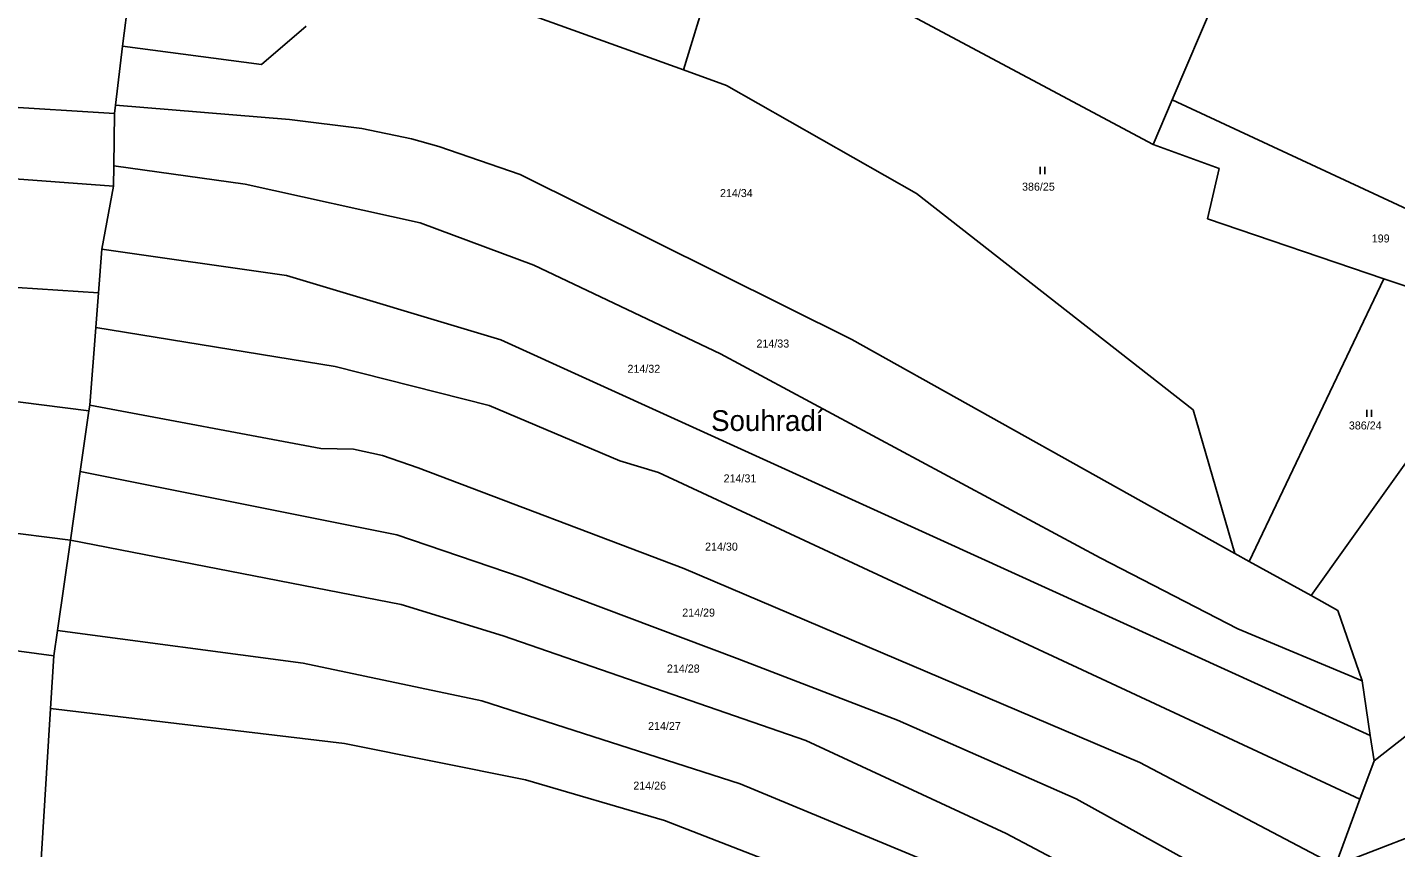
# Model space of a CAD drawing. Extents: x -791032 to -787751, y -1106872 to -1104403.
# Drawn here: x -789521.6 to -789231, y -1105221.6 to -1105047.4 of the extents above; entities that cross this region are included whole.
import ezdxf

# ---------------------------------------------------------------- set-up
doc = ezdxf.new("R2010")
doc.units = 0
for name, color, linetype in [('Vrstva 1', 7, 'Continuous'), ('Vrstva 14', 7, 'Continuous'), ('Vrstva 23', 7, 'Continuous'), ('Vrstva 39', 7, 'Continuous')]:
    doc.layers.add(name, color=color, linetype=linetype)

msp = doc.modelspace()

# ---------------------------------------------------------------- linework, layer by layer
at = {"layer": 'Vrstva 1'}
for p, q in [((-789501.39, -1105051.37), (-789499.01, -1105031.98)), ((-789382.28, -1105056.43), (-789376.17, -1105036.47)), ((-789382.28, -1105056.43), (-789423.8, -1105041.43)), ((-789278.51, -1105062.82), (-789269.38, -1105041.33)), ((-789282.53, -1105072.29), (-789335.91, -1105043.8)), ((-789462.42, -1105047.11), (-789471.88, -1105055.3)), ((-789502.93, -1105063.93), (-789501.39, -1105051.37)), ((-789501.39, -1105051.37), (-789471.88, -1105055.3)), ((-789373.13, -1105059.74), (-789382.28, -1105056.43)), ((-789332.82, -1105082.7), (-789373.13, -1105059.74)), ((-789282.53, -1105072.29), (-789278.51, -1105062.82)), ((-789278.51, -1105062.82), (-789222.93, -1105088.68)), ((-789528.49, -1105064.11), (-789503.15, -1105065.68)), ((-789503.15, -1105065.68), (-789503.28, -1105076.82)), ((-789503.15, -1105065.68), (-789502.93, -1105063.93)), ((-789502.93, -1105063.93), (-789465.99, -1105066.96)), ((-789465.99, -1105066.96), (-789450.6, -1105068.89)), ((-789450.6, -1105068.89), (-789440.07, -1105071.04)), ((-789440.07, -1105071.04), (-789434.22, -1105072.71)), ((-789282.53, -1105072.29), (-789268.5, -1105077.4)), ((-789434.22, -1105072.71), (-789416.96, -1105078.67)), ((-789503.33, -1105081.13), (-789552.47, -1105077.5)), ((-789503.28, -1105076.82), (-789503.33, -1105081.13)), ((-789503.28, -1105076.82), (-789475.35, -1105080.72)), ((-789268.5, -1105077.4), (-789271.02, -1105088.05)), ((-789505.83, -1105094.52), (-789503.33, -1105081.13)), ((-789475.35, -1105080.72), (-789438.22, -1105088.93)), ((-789416.96, -1105078.67), (-789346.54, -1105113.7)), ((-789274.03, -1105128.66), (-789332.82, -1105082.7)), ((-789438.22, -1105088.93), (-789414.08, -1105097.9)), ((-789271.02, -1105088.05), (-789233.54, -1105100.77)), ((-789506.54, -1105103.75), (-789505.83, -1105094.52)), ((-789505.83, -1105094.52), (-789466.58, -1105100.1)), ((-789414.08, -1105097.9), (-789374.45, -1105116.72)), ((-789506.54, -1105103.75), (-789547.8, -1105101.04)), ((-789466.58, -1105100.1), (-789421.07, -1105113.78)), ((-789262.14, -1105160.82), (-789233.54, -1105100.77)), ((-789233.54, -1105100.77), (-789207.36, -1105109.66)), ((-789507.11, -1105111.11), (-789506.54, -1105103.75)), ((-789249, -1105168.08), (-789207.36, -1105109.66)), ((-789508.39, -1105127.62), (-789507.11, -1105111.11)), ((-789507.11, -1105111.11), (-789456.26, -1105119.41)), ((-789327.7, -1105156.26), (-789421.07, -1105113.78)), ((-789346.54, -1105113.7), (-789265.23, -1105159.11)), ((-789374.45, -1105116.72), (-789293.78, -1105160.04)), ((-789456.26, -1105119.41), (-789423.56, -1105127.68)), ((-789508.57, -1105128.87), (-789537.11, -1105125.17)), ((-789508.57, -1105128.87), (-789508.39, -1105127.62)), ((-789508.39, -1105127.62), (-789459.31, -1105136.81)), ((-789423.56, -1105127.68), (-789395.8, -1105139.44)), ((-789510.41, -1105141.76), (-789508.57, -1105128.87)), ((-789274.03, -1105128.66), (-789265.23, -1105159.11)), ((-789459.31, -1105136.81), (-789452.35, -1105136.97)), ((-789452.35, -1105136.97), (-789446.18, -1105138.34)), ((-789446.18, -1105138.34), (-789438.65, -1105140.93)), ((-789512.49, -1105156.3), (-789510.41, -1105141.76)), ((-789510.41, -1105141.76), (-789443.14, -1105155.21)), ((-789438.65, -1105140.93), (-789382.23, -1105162.32)), ((-789395.8, -1105139.44), (-789387.62, -1105141.97)), ((-789238.63, -1105211.34), (-789387.62, -1105141.97)), ((-789530.73, -1105153.98), (-789512.49, -1105156.3)), ((-789515.24, -1105175.51), (-789512.49, -1105156.3)), ((-789512.49, -1105156.3), (-789442.27, -1105169.99)), ((-789443.14, -1105155.21), (-789416.77, -1105164.2)), ((-789236.44, -1105197.78), (-789327.7, -1105156.26)), ((-789262.14, -1105160.82), (-789265.23, -1105159.11)), ((-789382.23, -1105162.32), (-789285.39, -1105203.5)), ((-789293.78, -1105160.04), (-789264.54, -1105175.17)), ((-789249, -1105168.08), (-789262.14, -1105160.82)), ((-789416.77, -1105164.2), (-789370.89, -1105181.46)), ((-789243.29, -1105171.23), (-789249, -1105168.08)), ((-789442.27, -1105169.99), (-789420.58, -1105176.66)), ((-789238.18, -1105186.22), (-789243.29, -1105171.23)), ((-789516, -1105180.86), (-789515.24, -1105175.51)), ((-789515.24, -1105175.51), (-789463.03, -1105182.46)), ((-789420.58, -1105176.66), (-789356.31, -1105198.89)), ((-789264.54, -1105175.17), (-789238.18, -1105186.22)), ((-789541.28, -1105177.43), (-789516, -1105180.86)), ((-789516, -1105180.86), (-789516.69, -1105192.05)), ((-789463.03, -1105182.46), (-789425.14, -1105190.45)), ((-789370.89, -1105181.46), (-789336.83, -1105194.56)), ((-789236.44, -1105197.78), (-789238.18, -1105186.22)), ((-789425.14, -1105190.45), (-789370.26, -1105208.04)), ((-789516.69, -1105192.05), (-789518.74, -1105225.28)), ((-789516.69, -1105192.05), (-789454.24, -1105199.49)), ((-789336.83, -1105194.56), (-789298.86, -1105211.23)), ((-789235.62, -1105203.21), (-789226.84, -1105196.33)), ((-789454.24, -1105199.49), (-789415.85, -1105207.22)), ((-789356.31, -1105198.89), (-789313.74, -1105218.64)), ((-789235.62, -1105203.21), (-789236.44, -1105197.78)), ((-789238.63, -1105211.34), (-789235.62, -1105203.21)), ((-789285.39, -1105203.5), (-789243.84, -1105225.4)), ((-789415.85, -1105207.22), (-789386.31, -1105215.88)), ((-789370.26, -1105208.04), (-789327.75, -1105225.68)), ((-789252.41, -1105236.92), (-789298.86, -1105211.23)), ((-789243.84, -1105225.4), (-789238.63, -1105211.34)), ((-789386.31, -1105215.88), (-789333.63, -1105236.24)), ((-789313.74, -1105218.64), (-789301.43, -1105225.11)), ((-789226.96, -1105218.88), (-789243.84, -1105225.4))]:
    msp.add_line(p, q, dxfattribs=at)
at = {"layer": 'Vrstva 23'}
for p, q in [((-789306.52, -1105078.55), (-789306.52, -1105077.05)), ((-789305.52, -1105077.05), (-789305.52, -1105078.55)), ((-789237.15, -1105130.1), (-789237.15, -1105128.6)), ((-789236.15, -1105128.6), (-789236.15, -1105130.1))]:
    msp.add_line(p, q, dxfattribs=at)

# ---------------------------------------------------------------- texts
at = {"layer": 'Vrstva 14'}
for s, p in [('386/25', (-789310.386, -1105082.08)), ('214/34', (-789374.535, -1105083.44)), ('199', (-789236.12, -1105093.08)), ('214/33', (-789366.789, -1105115.4)), ('214/32', (-789394.179, -1105120.76)), ('386/24', (-789240.975, -1105132.8)), ('214/31', (-789373.762, -1105144.04)), ('214/30', (-789377.698, -1105158.53)), ('214/29', (-789382.549, -1105172.54)), ('214/28', (-789385.798, -1105184.42)), ('214/27', (-789389.805, -1105196.63)), ('214/26', (-789392.939, -1105209.3))]:
    msp.add_text(s, height=1.7, dxfattribs=at).set_placement(p)
at = {"layer": 'Vrstva 39'}
msp.add_text('Souhradí', height=4.4, dxfattribs=at).set_placement((-789376.43, -1105133.12))

doc.saveas('drawing.dxf')
